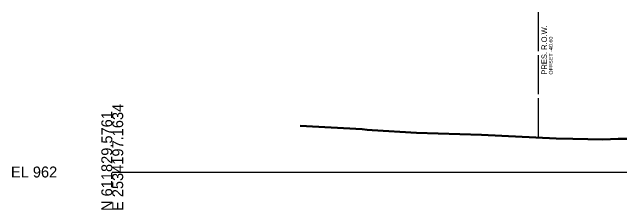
# Model space of a CAD drawing. Extents: x -192 to 2669, y -25 to 8040.
# Drawn here: x -25.7 to 130.3, y 3990.3 to 4041 of the extents above; entities that cross this region are included whole.
import ezdxf

# ---------------------------------------------------------------- set-up
doc = ezdxf.new("R2010")
doc.units = 0
for name, color, linetype in [('DESIGN - SHEET - Light Grid', 7, 'Continuous'), ('SURVEY - GROUND - Bottom of Topsoil Layer', 7, 'Continuous'), ('SURVEY - GROUND - Top of Ground', 7, 'Continuous'), ('SURVEY - PROPERTY - ROW Lines', 7, 'Continuous'), ('SURVEY - PROPERTY - ROW Lines Text', 7, 'Continuous')]:
    doc.layers.add(name, color=color, linetype=linetype)

msp = doc.modelspace()

# ---------------------------------------------------------------- linework, layer by layer
at = {"layer": 'DESIGN - SHEET - Light Grid'}
msp.add_line((0, 4000), (150, 4000), dxfattribs=at)
at = {"layer": 'SURVEY - GROUND - Bottom of Topsoil Layer'}
for p, q in [((48.2, 4011.72), (64.13, 4010.86)), ((64.13, 4010.86), (65.43, 4010.75)), ((65.43, 4010.75), (66.71, 4010.66)), ((66.71, 4010.66), (78.06, 4009.95)), ((78.06, 4009.95), (94.8, 4009.42)), ((94.8, 4009.42), (113.93, 4008.49)), ((113.93, 4008.49), (118.16, 4008.39)), ((118.16, 4008.39), (125.86, 4008.28)), ((125.86, 4008.28), (129.87, 4008.39)), ((129.87, 4008.39), (132.36, 4008.44))]:
    msp.add_line(p, q, dxfattribs=at)
at = {"layer": 'SURVEY - GROUND - Top of Ground'}
msp.add_lwpolyline([(48.2, 4011.97), (64.13, 4011.11), (65.43, 4011), (66.71, 4010.91), (78.06, 4010.2), (94.8, 4009.67), (113.93, 4008.74), (118.16, 4008.64), (125.86, 4008.53), (129.87, 4008.64), (132.36, 4008.69)], dxfattribs=at)
at = {"layer": 'SURVEY - PROPERTY - ROW Lines'}
for p, q in [((109.4, 4030.96), (109.4, 4040.96)), ((109.4, 4019.96), (109.4, 4029.96)), ((109.4, 4008.96), (109.4, 4018.96))]:
    msp.add_line(p, q, dxfattribs=at)

# ---------------------------------------------------------------- texts
at = {"layer": 'DESIGN - SHEET - Light Grid'}
for s, p in [('E 2534197.1634', (2.8, 3990)), ('N 611829.5761', (0, 3990))]:
    msp.add_text(s, height=2.8, rotation=90, dxfattribs=at).set_placement(p)
msp.add_text('EL 962', height=2.8, dxfattribs=at).set_placement((-26, 3998.6))
at = {"layer": 'SURVEY - PROPERTY - ROW Lines Text'}
for s, height, p in [('PRES. R.O.W.', 1.4, (111.55, 4024.96)), ('OFFSET -40.60', 1, (113.05, 4024.96))]:
    msp.add_text(s, height=height, rotation=90, dxfattribs=at).set_placement(p)

doc.saveas('drawing.dxf')
